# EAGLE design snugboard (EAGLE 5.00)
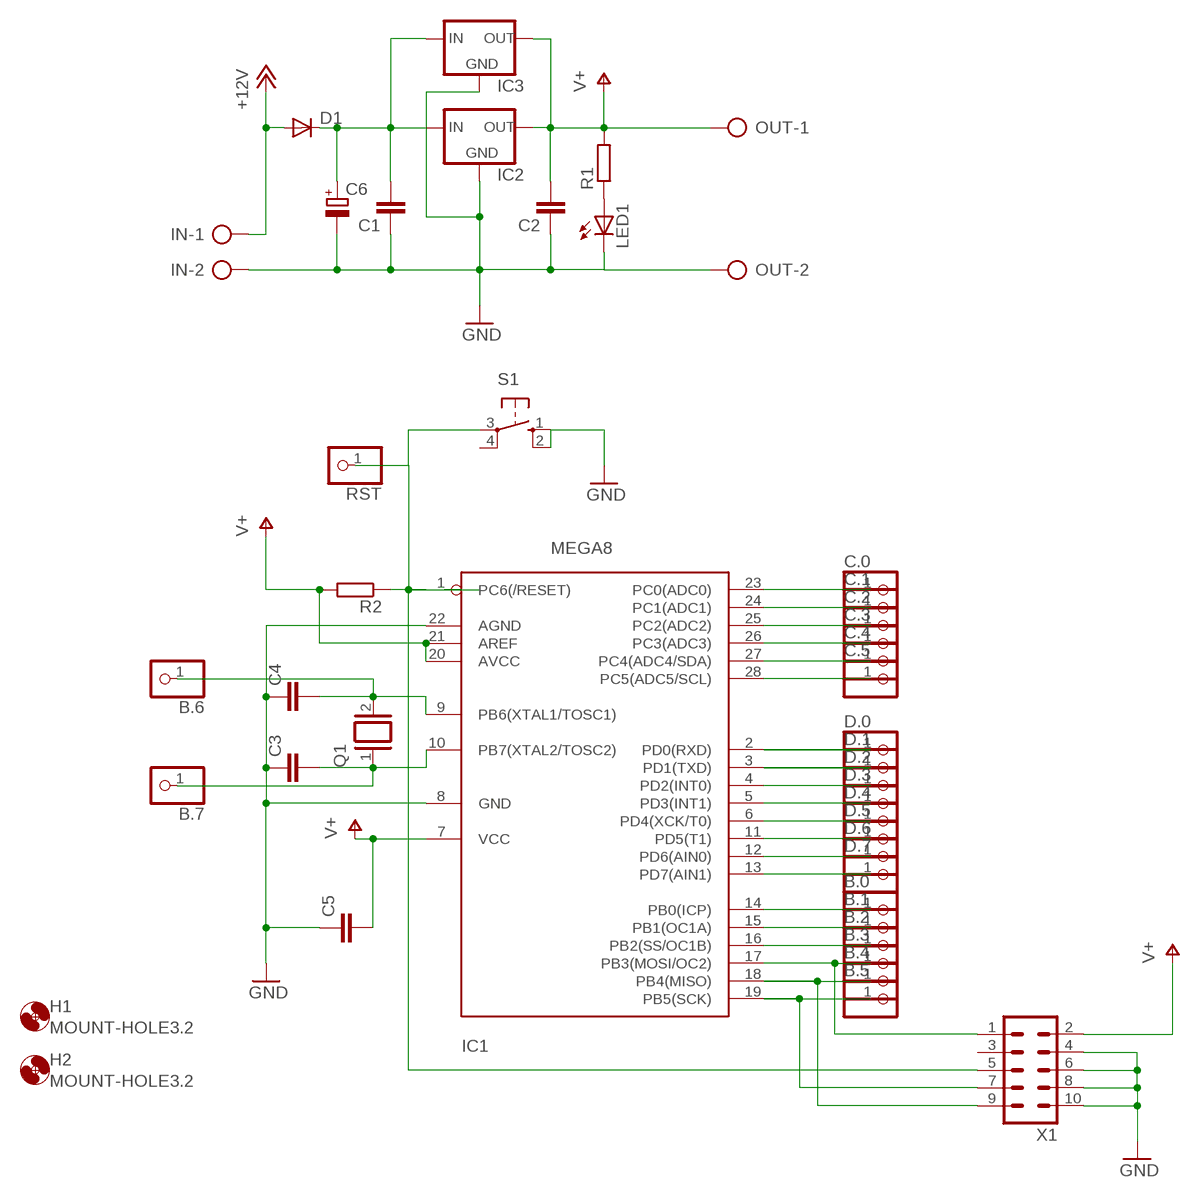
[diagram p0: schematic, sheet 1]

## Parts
B.0  PINHD-1X1  [1X01]
B.1  PINHD-1X1  [1X01]
B.2  PINHD-1X1  [1X01]
B.3  PINHD-1X1  [1X01]
B.4  PINHD-1X1  [1X01]
B.5  PINHD-1X1  [1X01]
B.6  PINHD-1X1  [1X01]
B.7  PINHD-1X1  [1X01]
C1  C2,5-3  [C2.5-3]
C2  C2,5-3  [C2.5-3]
C3  C2,5-3  [C2.5-3]
C4  C2,5-3  [C2.5-3]
C5  C2,5-3  [C2.5-3]
C6  CPOL-EUE2,5-6E  [E2,5-6E]
C.0  PINHD-1X1  [1X01]
C.1  PINHD-1X1  [1X01]
C.2  PINHD-1X1  [1X01]
C.3  PINHD-1X1  [1X01]
C.4  PINHD-1X1  [1X01]
C.5  PINHD-1X1  [1X01]
D1  1N4004  [DO41-10]
D.0  PINHD-1X1  [1X01]
D.1  PINHD-1X1  [1X01]
D.2  PINHD-1X1  [1X01]
D.3  PINHD-1X1  [1X01]
D.4  PINHD-1X1  [1X01]
D.5  PINHD-1X1  [1X01]
D.6  PINHD-1X1  [1X01]
D.7  PINHD-1X1  [1X01]
H1  MOUNT-HOLE3.2  [3,2]
H2  MOUNT-HOLE3.2  [3,2]
IC1  MEGA8  MEGA8-P  [DIL28-3]
IC2  78XXL  [78XXL]
IC3  78XXS  [78XXS]
IN  AK500/2  [AK500/2]
LED1  LED3MM  [LED3MM]
OUT  AK500/2  [AK500/2]
Q1  XTAL/S  [QS]
R1  R-EU_0207/2V  [0207/2V]
R2  R-EU_0207/2V  [0207/2V]
RST  PINHD-1X1  [1X01]
S1  10-XX  [B3F-10XX]
X1  ML10  [ML10]

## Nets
+12V: D1.A IN.1
GND: C1.1 C2.1 C3.1 C4.1 C5.1 C6.- IC1.8(GND) IC1.22(AGND) IC2.GND IC3.GND IN.2 LED1.K(C) OUT.2 S1.1(S) S1.2(S1) X1.4 X1.6 X1.8 X1.10
N$1: B.6.1 C4.2 IC1.9(PB6(XTAL1/TOSC1)) Q1.2
N$2: B.7.1 C3.2 IC1.10(PB7(XTAL2/TOSC2)) Q1.1
N$3: C.0.1 IC1.23(PC0(ADC0))
N$4: LED1.A R1.1
N$5: C.1.1 IC1.24(PC1(ADC1))
N$6: C.2.1 IC1.25(PC2(ADC2))
N$7: C.3.1 IC1.26(PC3(ADC3))
N$8: C.4.1 IC1.27(PC4(ADC4/SDA))
N$9: C.5.1 IC1.28(PC5(ADC5/SCL))
N$10: D.2.1 IC1.4(PD2(INT0))
N$11: D.3.1 IC1.5(PD3(INT1))
N$12: D.4.1 IC1.6(PD4(XCK/T0))
N$16: C1.2 C6.+ D1.C IC2.IN IC3.IN
N$17: D.1.1 IC1.3(PD1(TXD))
N$18: D.0.1 IC1.2(PD0(RXD))
N$23: D.5.1 IC1.11(PD5(T1))
N$24: IC1.1(PC6(/RESET)) R2.1 RST.1 S1.3(P) X1.5
N$25: D.6.1 IC1.12(PD6(AIN0))
N$26: D.7.1 IC1.13(PD7(AIN1))
N$27: B.0.1 IC1.14(PB0(ICP))
N$28: B.3.1 IC1.17(PB3(MOSI/OC2)) X1.1
N$29: B.5.1 IC1.19(PB5(SCK)) X1.7
N$30: B.4.1 IC1.18(PB4(MISO)) X1.9
N$31: B.1.1 IC1.15(PB1(OC1A))
N$32: B.2.1 IC1.16(PB2(SS/OC1B))
V+: C2.2 C5.2 IC1.7(VCC) IC1.20(AVCC) IC1.21(AREF) IC2.OUT IC3.OUT OUT.1 R1.2 R2.2 X1.2
Unconnected: S1.4(P1) X1.3

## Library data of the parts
B.0 B.1-B.7 C.0 C.1-C.5 D.0 D.1-D.7 RST = pinhead:PINHD-1X1: PIN HEADER
C1-C5 = capacitor-wima:C: CAPACITOR
C6 = rcl:CPOL-EU: POLARIZED CAPACITOR, European symbol
D1 = diode:1N4004: DIODE
H1 H2 = holes:MOUNT-HOLE: MOUNTING HOLE with drill center marker
IC1 = avr:MEGA8-P: MICROCONTROLLER 8 Kbytes FLASH 1 kbytes SRAM 512 bytes EEPROM USART 4-channel 10 bit ADC 2-channel 8 bit ADC
IC2 = v-reg:78XXL: VOLTAGE REGULATOR
IC3 = v-reg:78XXS: VOLTAGE REGULATOR
IN OUT = con-ptr500:AK500/2: CONNECTOR
LED1 = led:LED: LED
Q1 = special:XTAL/S: CRYSTAL
R1 R2 = rcl:R-EU_: RESISTOR, European symbol
S1 = switch-omron:10-XX: OMRON SWITCH
X1 = con-harting-ml:ML10: HARTING

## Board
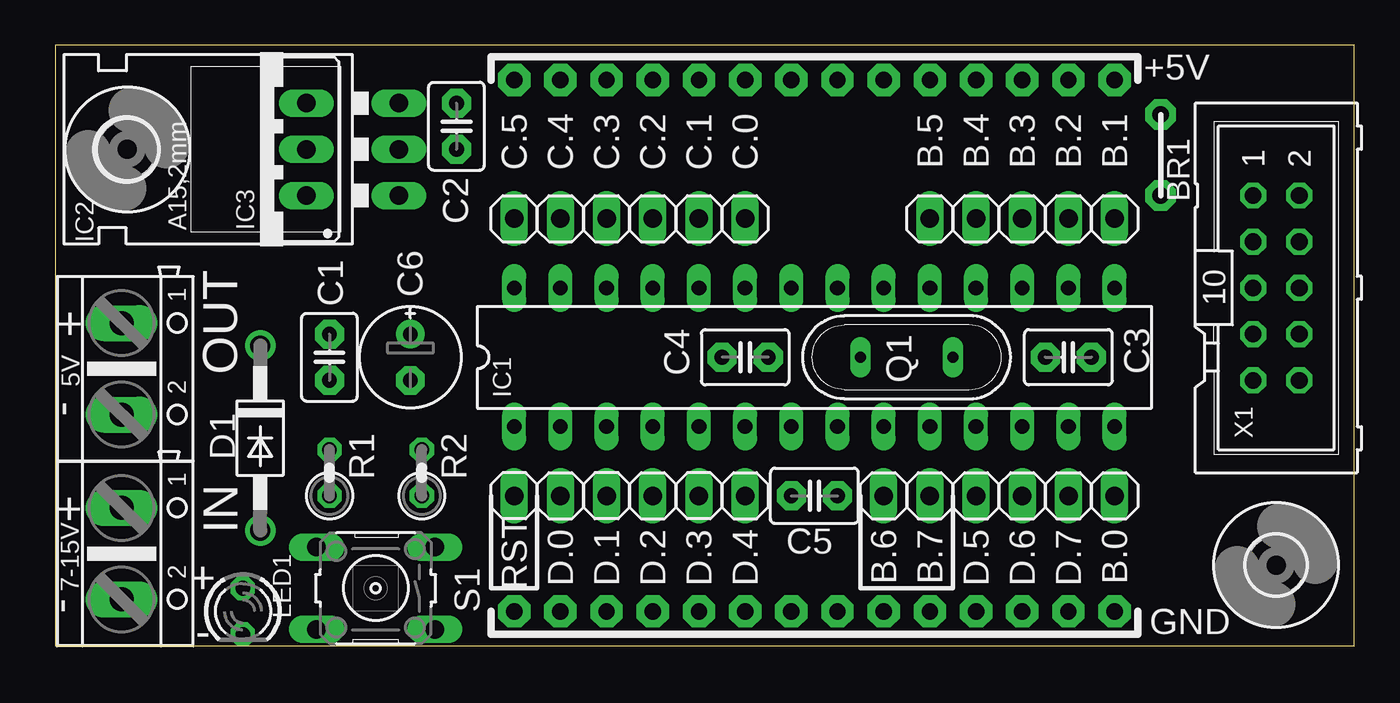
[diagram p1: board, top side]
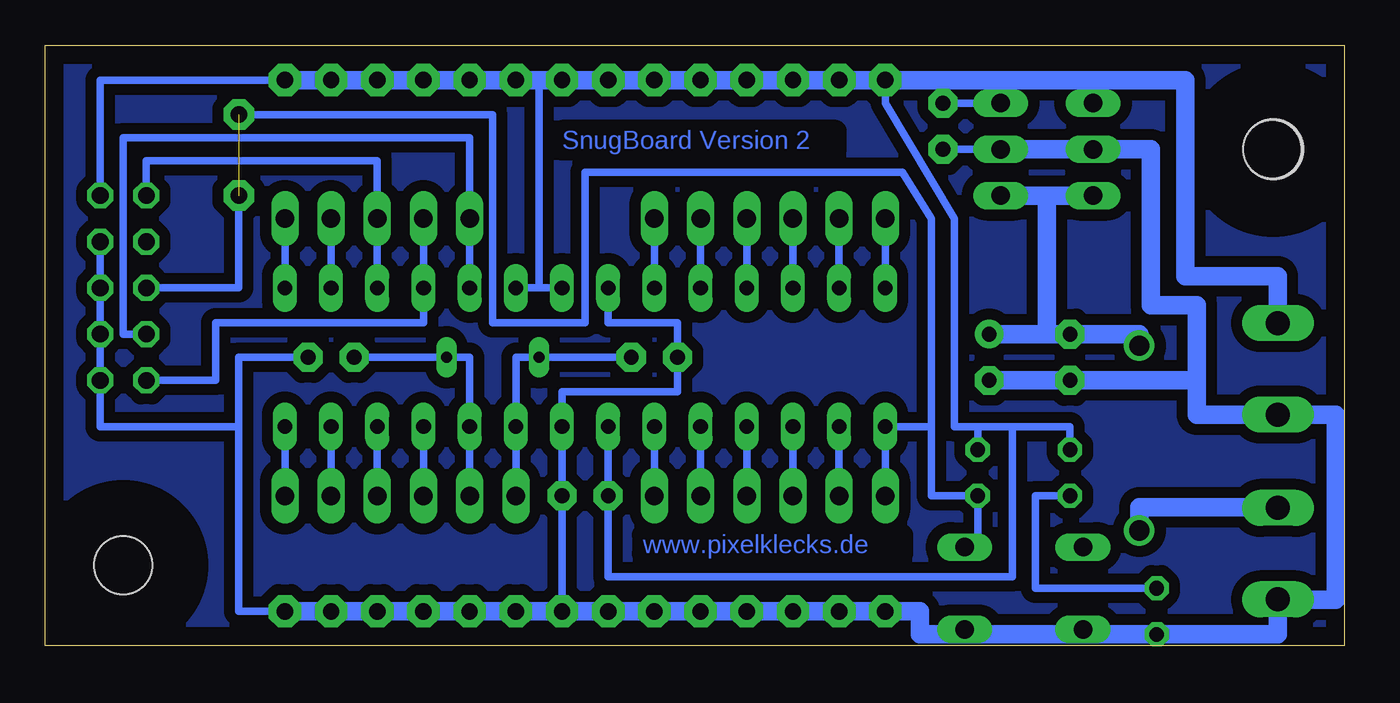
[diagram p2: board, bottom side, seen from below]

Size 71.42 x 33.01 mm. Coordinates in mm from the lower left corner, seen from the top.
Outline: 0,0 71.42,0 71.42,33.01 0,33.01 0,0
Copper layers (1*16): Top 0.035mm / dielectric 1.5mm / Bottom 0.035mm
Design rules "default": minimum track width 10mil, minimum drill 24mil, track to track 8mil, track to pad 8mil, pad to pad 8mil, via to via 8mil, smd to smd 8mil, copper to edge 40mil, drill to drill 8mil, minimum pad ring 10mil, minimum via ring 8mil, stop-mask expansion 4mil, vias tented up to drill 0mil, thermal gap 10mil

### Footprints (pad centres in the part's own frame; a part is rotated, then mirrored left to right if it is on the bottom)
1X01 = drill 1.016 long: 1 0,0
C2.5-3 = drill 0.813 pad 1.6 octagon: 1 -1.27,0; 2 1.27,0
E2,5-6E = drill 0.813 pad 1.575 round: + -1.27,0 | drill 0.813 pad 1.575 octagon: - 1.27,0
DO41-10 = drill 1.118 round: A 5.08,0; C -5.08,0
3,2 = hole 3.2: 0,0
DIL28-3 = drill 0.813 long: 1 -16.51,-3.81; 2 -13.97,-3.81; 3 -11.43,-3.81; 4 -8.89,-3.81; 5 -6.35,-3.81; 6 -3.81,-3.81; 7 -1.27,-3.81; 8 1.27,-3.81; 9 3.81,-3.81; 10 6.35,-3.81; 11 8.89,-3.81; 12 11.43,-3.81; 13 13.97,-3.81; 14 16.51,-3.81; 15 16.51,3.81; 16 13.97,3.81; 17 11.43,3.81; 18 8.89,3.81; 19 6.35,3.81; 20 3.81,3.81; 21 1.27,3.81; 22 -1.27,3.81; 23 -3.81,3.81; 24 -6.35,3.81; 25 -8.89,3.81; 26 -11.43,3.81; 27 -13.97,3.81; 28 -16.51,3.81
78XXL = drill 1.016 long: GND 0,-3.81; IN -2.54,-3.81; OUT 2.54,-3.81 | hole 3.302: 0,11.176
78XXS = drill 1.016 long: GND 0,-2.54; IN -2.54,-2.54; OUT 2.54,-2.54
AK500/2 = drill 1.321 long: 1 -2.515,0; 2 2.515,0
LED3MM = drill 0.813 octagon: A -1.27,0; K 1.27,0
QS = drill 0.61 long: 1 -2.54,0; 2 2.54,0
0207/2V = drill 0.813 octagon: 1 -1.27,0; 2 1.27,0
B3F-10XX = drill 1.016 long: 1 -3.251,2.261; 2 3.251,2.261; 3 -3.251,-2.261; 4 3.251,-2.261
ML10 = drill 0.914 octagon: 1 -5.08,-1.27; 2 -5.08,1.27; 3 -2.54,-1.27; 4 -2.54,1.27; 5 0,-1.27; 6 0,1.27; 7 2.54,-1.27; 8 2.54,1.27; 9 5.08,-1.27; 10 5.08,1.27

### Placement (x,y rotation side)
B.0  58.26,8.25 90 top
B.1  58.26,23.49 90 top
B.2  55.72,23.49 90 top
B.3  53.18,23.49 90 top
B.4  50.63,23.49 90 top
B.5  48.09,23.49 90 top
B.6  45.55,8.25 90 top
B.7  48.09,8.25 90 top
C1  15.08,15.87 90 top
C2  22.06,28.57 90 top
C3  55.72,15.87 180 top
C4  37.94,15.87 0 top
C5  41.74,8.25 180 top
C6  19.52,15.87 270 top
C.0  37.94,23.49 90 top
C.1  35.4,23.49 90 top
C.2  32.86,23.49 90 top
C.3  30.32,23.49 90 top
C.4  27.78,23.49 90 top
C.5  25.23,23.49 90 top
D1  11.27,11.43 270 top
D.0  27.78,8.25 90 top
D.1  30.32,8.25 270 top
D.2  32.86,8.25 90 top
D.3  35.4,8.25 270 top
D.4  37.94,8.25 90 top
D.5  50.63,8.25 90 top
D.6  53.18,8.25 90 top
D.7  55.72,8.25 90 top
H1  3.96,27.3 0 top
H2  67.14,4.44 0 top
IC1  41.74,15.87 0 top
IC2  15.08,27.3 90 top
IC3  11.27,27.3 90 top
IN  3.65,5.08 270 top
LED1  10.31,1.9 270 top
OUT  3.65,15.23 270 top
Q1  46.83,15.87 180 top
R1  15.08,9.52 90 top
R2  20.16,9.52 90 top
RST  25.23,8.25 270 top
S1  17.62,3.17 180 top
X1  67.14,19.68 270 top

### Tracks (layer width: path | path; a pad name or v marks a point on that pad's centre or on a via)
+12V
  Bottom 0.813: IN.1 3.65,7.62
  Bottom 1.016: 3.65,7.62 11.27,7.62 D1.A
GND  (via drill 0.9 pad 1.78)
  Bottom 0.406: IC1.22 40.48,17.77 36.66,17.77 C4.1 36.66,13.96 43.02,13.96 IC1.8 C5.1 v43.02,1.9 | X1.4 X1.6 X1.8 | X1.8 X1.10 | X1.8 68.41,12.06 60.8,12.06 | 60.8,1.9 60.8,12.06 | 60.8,12.06 60.8,15.87 | 60.8,15.87 C3.1 | 60.8,1.9 60.8,15.87 | v58.26,1.9 60.8,1.9 | 20.79,0.63 20.87,0.55 | 14.44,0.63 15.63,0.55 | IC2.GND C2.1 | 8.09,14.59 10.65,14.59 8.11,14.6 8.09,17.14
  Bottom 0.813: 3.65,12.7 OUT.2 | 20.87,0.55 S1.1 | 15.63,0.55 S1.2 | 8.09,17.14 8.09,14.59 | 3.65,2.54 IN.2
  Bottom 1.016: v58.26,1.9 v55.72,1.9 v53.18,1.9 v50.63,1.9 v48.09,1.9 v45.55,1.9 v43.02,1.9 v40.48,1.9 v37.94,1.9 v35.4,1.9 v32.86,1.9 v30.32,1.9 v27.78,1.9 v25.23,1.9 23.33,1.9 23.33,0.63 20.79,0.63 14.44,0.63 LED1.K 3.65,0.63 3.65,2.54 0.47,2.54 0.47,12.7 3.65,12.7 | IC2.GND IC3.GND 10.63,27.3 10.63,18.73 8.09,18.73 8.09,17.14 8.09,12.72 OUT.2 | 8.11,14.6 C1.1 C6.-
N$1
  Bottom 0.406: B.6.1 IC1.9 45.55,15.87 Q1.2 C4.2
N$2
  Bottom 0.406: B.7.1 IC1.10 48.09,15.87 Q1.1 C3.2
N$3
  Bottom 0.406: IC1.23 C.0.1
N$4
  Bottom 0.406: 16.98,4.12 16.98,3.7 | 16.98,4.12 16.98,8.25 R1.1 | LED1.A 16.98,3.17 16.98,4.12
N$5
  Bottom 0.406: IC1.24 C.1.1
N$6
  Bottom 0.406: IC1.25 C.2.1
N$7
  Bottom 0.406: IC1.26 C.3.1
N$8
  Bottom 0.406: IC1.27 C.4.1
N$9
  Bottom 0.406: IC1.28 C.5.1
N$10
  Bottom 0.406: D.2.1 IC1.4
N$11
  Bottom 0.406: D.3.1 IC1.5
N$12
  Bottom 0.406: D.4.1 IC1.6
N$13
  pour Bottom (isolate 0.61): 0.15,33.02 71.59,33.02 71.59,0 0.15,0
N$16
  Bottom 1.016: D1.C 11.27,17.14 | 11.27,17.14 16.35,17.14 | 16.35,24.76 IC2.IN | 16.35,17.14 16.35,24.76 | 16.35,17.14 C6.+ | 11.27,17.14 C1.2 | 16.35,24.76 IC3.IN
N$17
  Bottom 0.406: D.1.1 IC1.3
N$18
  Bottom 0.406: D.0.1 IC1.2
N$23
  Bottom 0.406: D.5.1 IC1.11
N$24  (via drill 0.9 pad 1.68)  (1 unrouted)
  Bottom 0.406: X1.5 60.8,19.68 v60.8,24.76 | 22.7,12.06 IC1.1 RST.1 | 22.7,12.06 22.7,23.49 24.28,26.03 41.74,26.03 41.74,17.75 46.83,17.75 46.83,29.2 v60.8,29.2 | 22.7,12.06 22.7,8.25 R2.1 20.16,5.43 S1.3
N$25
  Bottom 0.406: D.6.1 IC1.12
N$26
  Bottom 0.406: D.7.1 IC1.13
N$27
  Bottom 0.406: B.0.1 IC1.14
N$28
  Bottom 0.406: IC1.17 B.3.1 53.18,26.66 65.88,26.66 X1.1
N$29
  Bottom 0.406: IC1.19 B.5.1 | IC1.19 B.5.1 | IC1.19 B.5.1 | B.5.1 48.09,27.93 67.14,27.93 67.14,17.14 X1.7
N$30
  Bottom 0.406: B.4.1 IC1.18 50.63,17.77 62.06,17.77 62.06,14.6 X1.9
N$31
  Bottom 0.406: IC1.15 B.1.1
N$32
  Bottom 0.406: IC1.16 B.2.1
V+  (via drill 0.9 pad 1.78)
  Bottom 0.406: C5.2 IC1.7 | v58.26,31.11 68.41,31.11 X1.2 | 44.29,19.68 IC1.20 | C5.2 IC1.7 | R1.2 15.08,12.06 18.25,12.06 | 20.16,12.06 18.25,12.06 | 20.16,12.06 R2.2 | C5.2 IC1.7 | C5.2 40.48,3.8 18.25,3.8 18.25,12.06 | 3.65,17.77 4.89,17.77 | IC2.OUT C2.2 | 44.29,19.68 IC1.21 | 44.29,31.11 44.29,19.68 | v25.23,31.11 25.23,29.84 21.43,23.49 21.43,12.06 20.16,12.06
  Bottom 0.813: OUT.1 3.65,17.77 | 44.29,31.11 v43.02,31.11 v40.48,31.11 v37.94,31.11 v35.4,31.11 v32.86,31.11 v30.32,31.11 v27.78,31.11 v25.23,31.11
  Bottom 1.016: v58.26,31.11 v55.72,31.11 v53.18,31.11 v50.63,31.11 v48.09,31.11 v45.55,31.11 44.29,31.11 v25.23,31.11 18.89,31.11 | 3.65,17.77 3.65,20.32 8.73,20.32 8.73,31.11 13.81,31.11 | 18.89,31.11 IC2.OUT | 13.81,31.11 18.89,31.11 | 13.81,31.11 IC3.OUT

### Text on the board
Bottom: SnugBoard Version 2 | www.pixelklecks.de
tPlace: BR1 | + | 5V | - | + | 7-15V | + | - | -
tNames: +5V | OUT | GND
